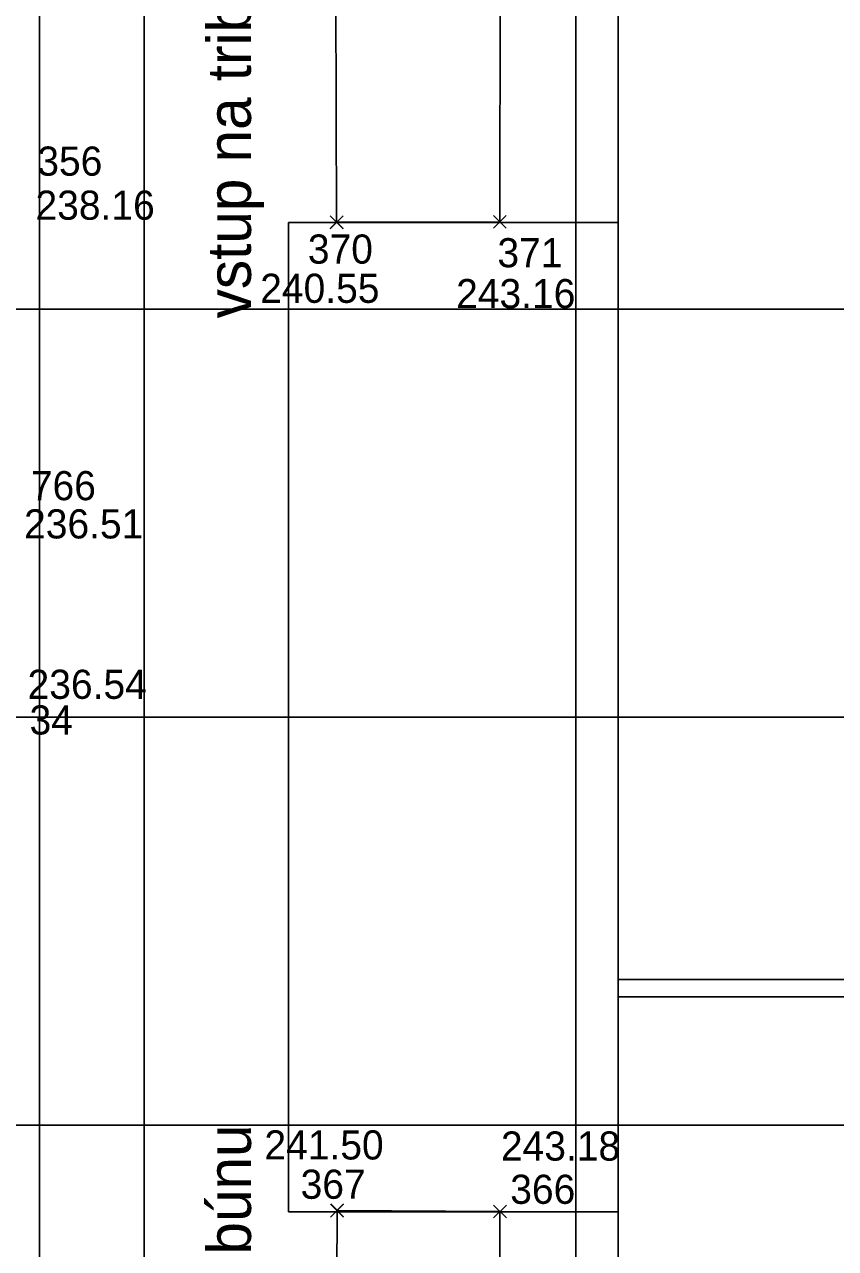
# Model space of a CAD drawing. Extents: x -264205 to -263659, y -1242401 to -1242060.
# Drawn here: x -263811.77 to -263797.86, y -1242205 to -1242184 of the extents above; entities that cross this region are included whole.
import ezdxf

# ---------------------------------------------------------------- set-up
doc = ezdxf.new("R2010")
doc.units = 0
for name, color, linetype in [('BOD_CISLO', 7, 'Continuous'), ('BOD_SYMBOL', 7, 'Continuous'), ('BOD_VYSKA', 7, 'Continuous'), ('KFA_SO_10-1_VSTUPY_TRIBUNA_C', 7, 'Continuous'), ('OBRUBNIKY_KOMUNIKACIE_PROJEKT', 7, 'Continuous'), ('OSI_STAVBY_KFA', 7, 'Continuous'), ('POPIS', 7, 'Continuous'), ('SITUACIA_DSP_2D', 7, 'Continuous')]:
    doc.layers.add(name, color=color, linetype=linetype)

msp = doc.modelspace()

# ---------------------------------------------------------------- linework, layer by layer
at = {"layer": 'BOD_SYMBOL'}
for p, q in [((-263806.53, -1242187.498), (-263806.309, -1242187.278)), ((-263806.309, -1242187.498), (-263806.53, -1242187.278)), ((-263806.53, -1242187.502), (-263806.308, -1242187.281)), ((-263806.308, -1242187.502), (-263806.53, -1242187.281)), ((-263803.731, -1242187.494), (-263803.51, -1242187.272)), ((-263803.51, -1242187.494), (-263803.731, -1242187.272)), ((-263806.524, -1242204.458), (-263806.302, -1242204.238)), ((-263806.302, -1242204.458), (-263806.524, -1242204.238)), ((-263806.52, -1242204.454), (-263806.299, -1242204.232)), ((-263806.299, -1242204.454), (-263806.52, -1242204.232)), ((-263803.729, -1242204.472), (-263803.508, -1242204.252)), ((-263803.508, -1242204.472), (-263803.729, -1242204.252))]:
    msp.add_line(p, q, dxfattribs=at)
at = {"layer": 'KFA_SO_10-1_VSTUPY_TRIBUNA_C'}
for p, q in [((-263806.431, -1242183.368), (-263806.419, -1242187.391)), ((-263806.413, -1242204.348), (-263806.434, -1242208.397))]:
    msp.add_line(p, q, dxfattribs=at)
for points in [[(-263806.419, -1242187.391), (-263806.42, -1242187.388), (-263803.621, -1242187.383), (-263803.615, -1242183.365), (-263806.431, -1242183.357), (-263806.431, -1242183.368)], [(-263806.434, -1242208.397), (-263806.431, -1242208.393), (-263803.61, -1242208.377), (-263803.618, -1242204.362), (-263806.41, -1242204.343), (-263806.413, -1242204.348)]]:
    msp.add_lwpolyline(points, dxfattribs=at)
at = {"layer": 'OBRUBNIKY_KOMUNIKACIE_PROJEKT'}
msp.add_line((-263801.593, -1242104.482), (-263801.593, -1242224.282), dxfattribs=at)
at = {"layer": 'OSI_STAVBY_KFA'}
for p, q in [((-263811.518, -1242083.237), (-263811.518, -1242246.707)), ((-263809.718, -1242083.237), (-263809.718, -1242246.707)), ((-263802.318, -1242083.237), (-263802.318, -1242246.707)), ((-263792.653, -1242188.882), (-263909.343, -1242188.882)), ((-263792.653, -1242195.882), (-263917.263, -1242195.882)), ((-263792.653, -1242202.882), (-263909.343, -1242202.882))]:
    msp.add_line(p, q, dxfattribs=at)
at = {"layer": 'SITUACIA_DSP_2D'}
for p, q in [((-263801.593, -1242104.482), (-263801.593, -1242224.282)), ((-263807.243, -1242187.394), (-263807.243, -1242204.369)), ((-263801.593, -1242187.394), (-263807.243, -1242187.394)), ((-263801.593, -1242187.394), (-263807.243, -1242187.394)), ((-263807.243, -1242187.394), (-263807.243, -1242204.369)), ((-263801.593, -1242204.369), (-263801.593, -1242187.394)), ((-263801.593, -1242204.369), (-263801.593, -1242187.394)), ((-263801.593, -1242200.382), (-263800.593, -1242200.382)), ((-263800.593, -1242200.382), (-263793.171, -1242200.383)), ((-263801.593, -1242200.682), (-263800.593, -1242200.682)), ((-263788.893, -1242200.682), (-263800.593, -1242200.682)), ((-263807.243, -1242204.369), (-263801.593, -1242204.369)), ((-263807.243, -1242204.369), (-263801.593, -1242204.369))]:
    msp.add_line(p, q, dxfattribs=at)

# ---------------------------------------------------------------- texts
at = {"layer": 'BOD_CISLO'}
for s, p in [('356', (-263811.553, -1242186.591)), ('370', (-263806.913, -1242188.1)), ('371', (-263803.662, -1242188.163)), ('766', (-263811.664, -1242192.159)), ('34', (-263811.686, -1242196.179)), ('367', (-263807.037, -1242204.144)), ('366', (-263803.442, -1242204.231))]:
    msp.add_text(s, height=0.5, dxfattribs=at).set_placement(p)
at = {"layer": 'BOD_VYSKA'}
for s, p in [('238.16', (-263811.584, -1242187.347)), ('240.55', (-263807.73, -1242188.773)), ('243.16', (-263804.37, -1242188.864)), ('236.51', (-263811.78, -1242192.815)), ('236.54', (-263811.72, -1242195.567)), ('241.50', (-263807.658, -1242203.47)), ('243.18', (-263803.602, -1242203.489))]:
    msp.add_text(s, height=0.5, dxfattribs=at).set_placement(p)
at = {"layer": 'POPIS'}
for p in [(-263807.889, -1242189.039), (-263807.889, -1242210.006)]:
    msp.add_text('vstup na tribúnu', height=0.75, rotation=90, dxfattribs=at).set_placement(p)

doc.saveas('drawing.dxf')
